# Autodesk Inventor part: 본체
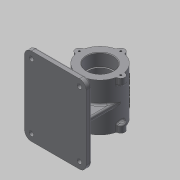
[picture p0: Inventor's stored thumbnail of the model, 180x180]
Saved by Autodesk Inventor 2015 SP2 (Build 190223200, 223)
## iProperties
Created: 2015-12
Part Number: 본체
Material: 일반
Document SubType Name: Modeling
Designer: AMC
Density: 1 g/cm^3
Appearance: 기본값
Author: AMC
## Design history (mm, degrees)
sketch "스케치1"
  geometry: C1 r 37 at (0, 0); 1 further point
  constraints: 1 centre point, 1 coincident
  dimensions: "d0" = 74 diameter of C1
extrude "돌출1" new body sketch "스케치1" distance "d1" = 85; taper "d2" = 0 deg
sketch "스케치2"
  geometry: L1 (-55, -70)-(55, -70); L2 (55, -70)-(55, -80); L3 (55, -80)-(-55, -80); L4 (-55, -80)-(-55, -70); 1 further point
  constraints: 8 end point, 2 parallel, 1 horizontal, 1 perpendicular
  dimensions: "d3" = 10 distance of L3.end L1.start; "d4" = 80 distance from line of L3 point (0, 0); "d5" = 110 distance of L2.end L3.end; "d6" = 55 distance from line of L4 point (0, 0)
extrude "돌출2" join sketch "스케치2" distance "d7" = 37.5; taper "d9" = 0 deg; dims "d8" = 102.5, "d10" = 0
node "작업 평면1"
sketch "스케치3"
  geometry: L1 (122.5, 117)-(107.5, 117); L2 (110.048, 124)-(122.5, 124); L3 (122.5, 124)-(122.5, 117); L4 (122.5, 43)-(122.5, 117) reference; L5 (37.5, 117)-(37.5, 43) reference; L6 (122.5, 43)-(122.5, 117) reference; L7 (122.5, 117)-(37.5, 117) reference; L8 (107.5, 117)-(110.048, 124); 1 further point
  constraints: 8 end point, 1 horizontal, 1 parallel
  dimensions: "d11" = 0 distance between parallel lines of L4 L3; "d12" = 0 distance between parallel lines of L7 L1; "d13" = 7 distance of L2.end L1.start; "d15" = 110 deg angle of L7 L8; "d16" = 15 distance of L1.start L1.end
revolve "회전1" sketch "스케치3" stored, may be unused: angle "d17" = 90 deg
sketch "스케치4"
  geometry: C1 r 21 at (0, 0); 1 further point
  constraints: 1 centre point, 1 coincident
  dimensions: "d21" = 42 diameter of C1
extrude "돌출3" cut sketch "스케치4" distance "d22" = 100; taper "d23" = 0 deg
sketch "스케치5"
  geometry: C1 r 23.5 at (0, 0); 1 further point
  constraints: 1 centre point, 1 coincident
  dimensions: "d24" = 47 diameter of C1
extrude "돌출4" cut sketch "스케치5" distance "d25" = 22; taper "d26" = 0 deg
sketch "스케치6"
  geometry: C1 r 23.5 at (0, 0); 1 further point
  constraints: 1 centre point, 1 coincident
  dimensions: "d27" = 47 diameter of C1
extrude "돌출5" cut sketch "스케치6" distance "d28" = 22; taper "d29" = 0 deg
sketch "스케치8"
  geometry: L1 (92, 84)-(18, 84); L2 (18, 84)-(18, 76); L3 (18, 76)-(92, 76); L4 (92, 76)-(92, 84); L5 (110, 0)-(110, 140) reference; L6 (0, 0)-(110, 0) reference; L7 (0, 0)-(0, 140) reference; L8 (110, 140)-(0, 140) reference; L9 (55, 84)-(55, 76); 1 further point
  constraints: 10 end point, 2 midpoint, 2 parallel, 1 horizontal, 1 perpendicular
  dimensions: "d40" = 8 distance of L3.end L1.start; "d41" = 76 distance between parallel lines of L6 L3; "d42" = 74 distance of L1.start L1.end; "d43" = 55 distance between parallel lines of L5 L9
extrude "돌출6" join sketch "스케치8" stored distance "d44" = 22; taper "d45" = 0 deg
sketch "스케치9"
  geometry: L1 (84, 10)-(84, 80) reference; L2 (84, 80)-(76, 80) reference; L3 (76, 10)-(76, 80) reference; L4 (84, 10)-(76, 10) reference; L5 (84, 10)-(84, 80) reference; L6 (0, 10)-(140, 10) reference; L7 (100.948, 43)-(105, 10); L8 (122.5, 43)-(37.5, 43) reference; 1 further point
  constraints: 2 end point, 2 point on line
  dimensions: "d50" = 97 deg angle of L6 L7; "d51" = 21 distance of L1.start L7.end
feature "리브1" sketch "스케치9" dims "d52" = 1, "d53" = 12, "d54" = 0, "d55" = 0, "d56" = 1, "d57" = 1
sketch "스케치10"
  geometry: L1 (122.5, 43)-(37.5, 43) reference; L2 (76, 10)-(76, 80) reference; L3 (0, 10)-(140, 10) reference; L4 (100.888, 43.49)-(105, 10) reference; L5 (59.052, 43)-(55, 10); 1 further point
  constraints: 2 end point, 2 point on line
  dimensions: "d58" = 97 deg angle of L3 L5; "d59" = 50 distance of L4.end L5.end
feature "리브2" sketch "스케치10" dims "d60" = 1, "d61" = 12, "d62" = 0, "d63" = 0, "d64" = 1, "d65" = 1
sketch "스케치11"
  geometry: L1 (110, 0)-(0, 0) reference; L2 (110, -140)-(110, 0) reference; L3 (0, -140)-(110, -140) reference; L4 (0, -140)-(0, 0) reference; C1 r 4 at (98, -12); 1 further point
  constraints: 1 centre point
  dimensions: "d66" = 8 diameter of C1; "d67" = 12 distance from line of L2 C1.centre; "d68" = 12 distance from line of L1 C1.centre
extrude "돌출7" cut sketch "스케치11" distance "d69" = 22; taper "d70" = 0 deg
fillet "모깎기1" dims "d77" = 12
fillet "모깎기2" dims "d78" = 0.3
chamfer "모따기1" distance "d79" = 1; stored, may be unused: second distance "d80" = 2, angle "d81" = 45 deg
fillet "모깎기4" dims "d83" = 3
fillet "모깎기5" dims "d84" = 3
fillet "모깎기6" dims "d85" = 3
fillet "모깎기7" dims "d86" = 3
fillet "모깎기8" dims "d87" = 3
sketch "스케치12"
  geometry: C1 r 24.5 at (0, 0) reference; A1 r 37 centre (0, 0) between (-9.104, 35.862) and (9.104, 35.863) reference; A2 r 3 centre (9.842, 38.77) between (6.889, 38.239) and (9.104, 35.863) reference; A3 r 7 centre (0, 37) between (6.889, 38.239) and (-6.889, 38.239) reference; A4 r 3 centre (-9.842, 38.77) between (-9.104, 35.862) and (-6.889, 38.239) reference; 2 further points
  constraints: 1 coincident
hole "구멍2" sketch "스케치12" at (0, 37) diameter "d88" = 3.242; stored, may be unused: countersink angle "d92" = 90 deg, drill point angle "d94" = 118 deg; dims "d89" = 9, "d90" = 4, "d91" = 2, "d93" = 11
node "작업 평면3"
node "작업 평면4"
node "작업 평면5"
node "작업 평면6"
sketch "스케치14"
  geometry: L1 (5, 27.5)-(5, -47.5); L2 (5, -47.5)-(-5, -47.5); L3 (-5, -47.5)-(-5, 27.5); L4 (-5, 27.5)-(5, 27.5); L5 (5, -10)-(-5, -10); L6 (18.921, 32.5)-(-18.921, 32.5) reference; 2 further points
  constraints: 3 midpoint, 2 end point, 1 vertical alignment, 2 other
  dimensions: "d102" = 42.5 distance between parallel lines of L6 L5; "d108" = 75 distance between parallel lines of L2 L4; "d109" = 10 distance between parallel lines of L3 L1
feature "엠보싱1" sketch "스케치14" dims "d11" = 0, "d12" = 0, "d13" = 7, "d15" = 110 deg, "d16" = 15, "d103" = 0.5, "d104" = 0
chamfer "모따기2" distance "d105" = 1; stored, may be unused: second distance "d106" = 2, angle "d107" = 45 deg
node "솔리드1"
pattern_linear "직사각형 패턴1" dims "d73" = 116, "d76" = 86
pattern_circular "원형 패턴3" dims "d96" = 360 deg
mirror "대칭3"
node "투영된 루프1"
node "투영된 루프3"
node "투영된 루프4"
node "투영된 루프5"
node "투영된 루프6"
